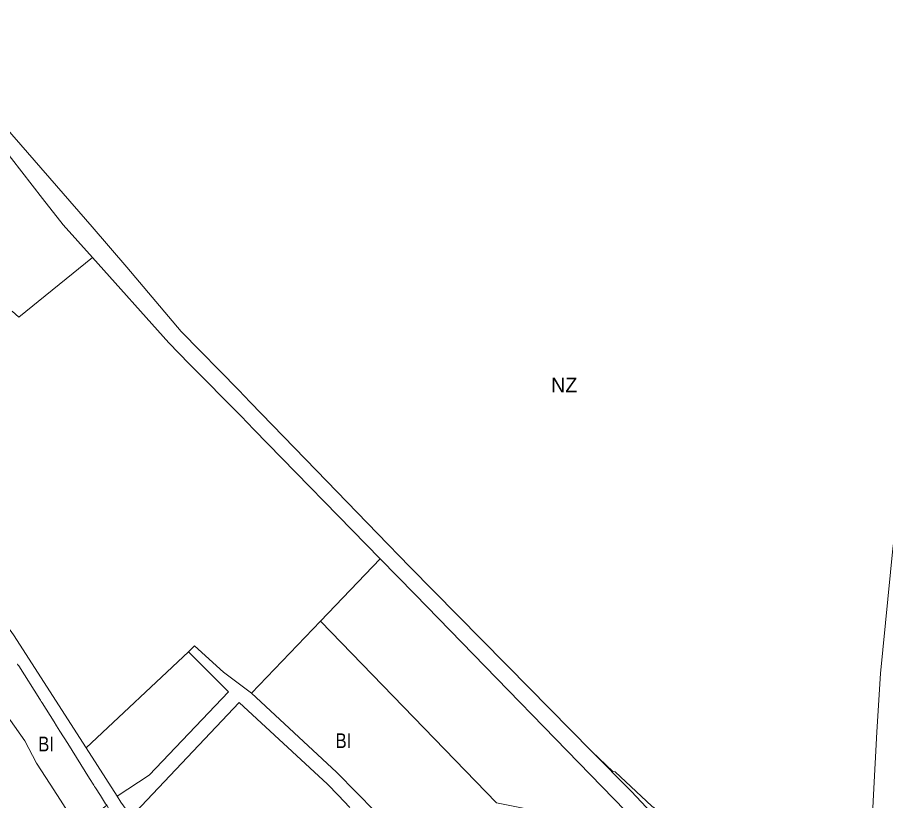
# Model space of a CAD drawing. Extents: x -650451 to -642268, y -1075216 to -1066610.
# Drawn here: x -646064 to -645357, y -1072336 to -1071698 of the extents above; entities that cross this region are included whole.
import ezdxf

# ---------------------------------------------------------------- set-up
doc = ezdxf.new("R2010")
doc.units = 0
doc.header["$LTSCALE"] = 4.8
for name, color, linetype, lineweight in [('15', 7, 'Continuous', 13), ('2', 7, 'Continuous', 13), ('24', 7, 'Continuous', 13), ('46', 7, 'Continuous', 13), ('48', 7, 'Continuous', 13)]:
    doc.layers.add(name, color=color, linetype=linetype, lineweight=lineweight)
doc.layers.add('62', color=7, linetype='Continuous')

msp = doc.modelspace()

# ---------------------------------------------------------------- linework, layer by layer
at = {"layer": '15'}
for points in [[(-645924.791, -1072215.043), (-645919.698, -1072210.262), (-645896.15, -1072231.57), (-645873.4, -1072248.61)], [(-645982.874, -1072332.508), (-645956.823, -1072315.504), (-645892.147, -1072247.526), (-645922.34, -1072217.38), (-645924.791, -1072215.043)], [(-645873.4, -1072248.61), (-645804.26, -1072313.11), (-645787.63, -1072329.98), (-645758.94, -1072359.08), (-645738.31, -1072371.43), (-645722.88, -1072380.66), (-645688.5, -1072384.55), (-645684.48, -1072384.17), (-645664.67, -1072382.33), (-645639.6, -1072379.99), (-645636.37, -1072379.57)], [(-645793.24, -1072341.76), (-645802.99, -1072331.72), (-645811.67, -1072322.79), (-645883.34, -1072256.32), (-645967.89, -1072345.59)], [(-645971.13, -1072349.41), (-645979.68, -1072337.49), (-645982.874, -1072332.508)]]:
    msp.add_lwpolyline(points, dxfattribs=at)
at = {"layer": '2'}
for p, q in [((-645873.4, -1072248.61), (-645817.219, -1072189.975)), ((-646008.065, -1072293.22), (-645924.791, -1072215.043))]:
    msp.add_line(p, q, dxfattribs=at)
for points in [[(-645817.219, -1072189.975), (-645674, -1072338), (-645650.78, -1072342.73), (-645636.37, -1072379.57)], [(-645924.791, -1072215.043), (-645922.34, -1072217.38), (-645892.147, -1072247.526), (-645956.823, -1072315.504), (-645982.874, -1072332.508), (-646008.065, -1072293.22)], [(-646064.24, -1072225.01), (-646063.86, -1072225.22), (-646063.53, -1072225.6)], [(-646063.53, -1072225.6), (-646062.87, -1072226.38), (-646045.76, -1072253.6), (-646045.18, -1072254.53), (-646044.91, -1072254.95)], [(-646014.64, -1072358.74), (-646016.43, -1072355.88), (-646026.55, -1072339.67), (-646037.37, -1072322.92), (-646048.32, -1072305.81), (-646057.93, -1072287.58), (-646069.73, -1072270.99), (-646071.3, -1072268.92), (-646081.08, -1072256.01), (-646091.27, -1072242.07), (-646101.18, -1072244.23)], [(-645636.37, -1072379.57), (-645639.6, -1072379.99), (-645664.67, -1072382.33), (-645684.48, -1072384.17), (-645688.5, -1072384.55), (-645722.88, -1072380.66), (-645738.31, -1072371.43), (-645758.94, -1072359.08), (-645787.63, -1072329.98), (-645804.26, -1072313.11), (-645873.4, -1072248.61)], [(-646044.91, -1072254.95), (-646044.65, -1072255.37), (-646043.84, -1072256.66), (-646034.08, -1072272.18)], [(-645967.89, -1072345.59), (-645883.34, -1072256.32), (-645811.67, -1072322.79), (-645802.99, -1072331.72), (-645793.24, -1072341.76)], [(-646034.08, -1072272.18), (-646032.07, -1072275.38), (-646029.41, -1072279.61), (-646023.06, -1072289.77), (-646012.41, -1072306.79)], [(-646012.41, -1072306.79), (-646005.26, -1072318.22), (-646001.8, -1072323.68), (-646001.17, -1072324.66)], [(-646001.17, -1072324.66), (-646000.38, -1072325.91), (-645996.41, -1072332.16), (-645992.15, -1072338.7), (-645991.3, -1072340), (-646014.64, -1072358.74)]]:
    msp.add_lwpolyline(points, dxfattribs=at)
at = {"layer": '24'}
for points in [[(-646209.322, -1071634.004), (-646200.32, -1071642.53), (-646160.52, -1071687.59), (-646150.43, -1071699.82), (-646003.04, -1071868.9), (-645975.01, -1071901.96), (-645930.57, -1071954.35), (-645883.81, -1072002.11), (-645874.53, -1072011.68), (-645820.57, -1072067.31), (-645770.72, -1072118.71), (-645744.42, -1072145.83), (-645666.4, -1072225.05), (-645664.88, -1072226.59), (-645596.405, -1072296.114)], [(-646002.93, -1071893.984), (-646026.64, -1071867.44), (-646043.49, -1071845.87), (-646077.32, -1071802.59), (-646087, -1071795), (-646104.5, -1071774.86), (-646122.16, -1071754.78)], [(-645768.649, -1072139.283), (-645871.4, -1072033.96), (-645881.95, -1072023.15), (-645924.1, -1071980.45), (-645940.8, -1071963.54), (-646002.93, -1071893.984)], [(-645546.82, -1072365.72), (-645559.34, -1072354.42), (-645740.45, -1072168.23), (-645768.649, -1072139.283)], [(-646095.44, -1072162.47), (-646067.08, -1072201.18), (-646008.065, -1072293.22), (-645982.874, -1072332.508), (-645979.68, -1072337.49), (-645971.13, -1072349.41), (-645919.08, -1072421.96), (-645916.34, -1072426.55), (-645898.28, -1072448.47)], [(-646063.53, -1072225.6), (-646063.86, -1072225.22), (-646064.24, -1072225.01)], [(-646044.91, -1072254.95), (-646045.18, -1072254.53), (-646045.76, -1072253.6), (-646062.87, -1072226.38), (-646063.53, -1072225.6)], [(-646034.08, -1072272.18), (-646043.84, -1072256.66), (-646044.65, -1072255.37), (-646044.91, -1072254.95)], [(-646029.41, -1072279.61), (-646032.07, -1072275.38), (-646034.08, -1072272.18)], [(-646001.17, -1072324.66), (-646001.8, -1072323.68), (-646005.26, -1072318.22), (-646012.41, -1072306.79), (-646023.06, -1072289.77), (-646029.41, -1072279.61)], [(-645596.405, -1072296.114), (-645564.4, -1072328.61), (-645547.72, -1072346.19), (-645532.07, -1072358.01), (-645531.65, -1072358.29), (-645528.27, -1072360.53), (-645519.57, -1072366.3), (-645438.64, -1072408.1), (-645437.6, -1072408.64), (-645434.19, -1072410.67), (-645399.77, -1072431.12), (-645342.284, -1072475.625), (-645333.62, -1072482.33), (-645290.76, -1072520.92), (-645271.74, -1072539.96), (-645249.9, -1072561.25)], [(-645996.41, -1072332.16), (-646000.38, -1072325.91), (-646001.17, -1072324.66)], [(-645987.91, -1072345.58), (-645988.89, -1072343.89), (-645991.21, -1072339.93), (-645991.3, -1072340), (-645992.15, -1072338.7), (-645996.41, -1072332.16)]]:
    msp.add_lwpolyline(points, dxfattribs=at)
at = {"layer": '46'}
for points in [[(-645596.405, -1072296.114), (-645664.88, -1072226.59), (-645666.4, -1072225.05), (-645744.42, -1072145.83), (-645770.72, -1072118.71), (-645820.57, -1072067.31), (-645874.53, -1072011.68), (-645883.81, -1072002.11), (-645930.57, -1071954.35), (-645975.01, -1071901.96), (-646003.04, -1071868.9), (-646150.43, -1071699.82), (-646160.52, -1071687.59), (-646200.32, -1071642.53), (-646209.322, -1071634.004)], [(-645269.077, -1071687.396), (-645274.868, -1071717.176), (-645286.175, -1071761.228), (-645300.076, -1071820.179), (-645313.153, -1071883.081), (-645326.343, -1071952.807), (-645334.118, -1072001.954), (-645339.455, -1072031.565), (-645344.819, -1072081.225), (-645351.358, -1072130.815), (-645361.317, -1072232.824), (-645364.435, -1072280.268), (-645366.951, -1072331.609), (-645370.624, -1072401.447), (-645372.228, -1072438.764), (-645387.894, -1072427.453), (-645414.631, -1072411.611), (-645448.831, -1072394.325), (-645488.64, -1072376.782), (-645515.437, -1072363.447), (-645547.593, -1072340.827), (-645577.33, -1072312.704), (-645579.217, -1072312.425), (-645596.405, -1072296.114)], [(-646068.317, -1071937.555), (-646062.91, -1071942.55), (-646002.93, -1071893.984)], [(-646002.93, -1071893.984), (-645940.8, -1071963.54), (-645924.1, -1071980.45), (-645881.95, -1072023.15), (-645871.4, -1072033.96), (-645768.649, -1072139.283), (-645817.219, -1072189.975), (-645873.4, -1072248.61)], [(-646008.065, -1072293.22), (-646067.08, -1072201.18), (-646095.44, -1072162.47), (-646123.06, -1072133.18)], [(-645873.4, -1072248.61), (-645896.15, -1072231.57), (-645919.698, -1072210.262), (-645924.791, -1072215.043), (-646008.065, -1072293.22)]]:
    msp.add_lwpolyline(points, dxfattribs=at)
at = {"layer": '48'}
msp.add_lwpolyline([(-646101.18, -1072244.23), (-646091.27, -1072242.07), (-646081.08, -1072256.01), (-646071.3, -1072268.92), (-646069.73, -1072270.99), (-646057.93, -1072287.58), (-646048.32, -1072305.81), (-646037.37, -1072322.92), (-646026.55, -1072339.67), (-646016.43, -1072355.88), (-646014.64, -1072358.74), (-646042.65, -1072381.23)], dxfattribs=at)

# ---------------------------------------------------------------- texts
at = {"layer": '62'}
msp.add_text('NZ', height=12, dxfattribs=at).set_placement((-645629.578, -1072003.82))
at = {"layer": '62', "width": 0.85}
for p in [(-646047.072, -1072296.094), (-645805.011, -1072293.409)]:
    msp.add_text('BI', height=12, dxfattribs=at).set_placement(p)

doc.saveas('drawing.dxf')
